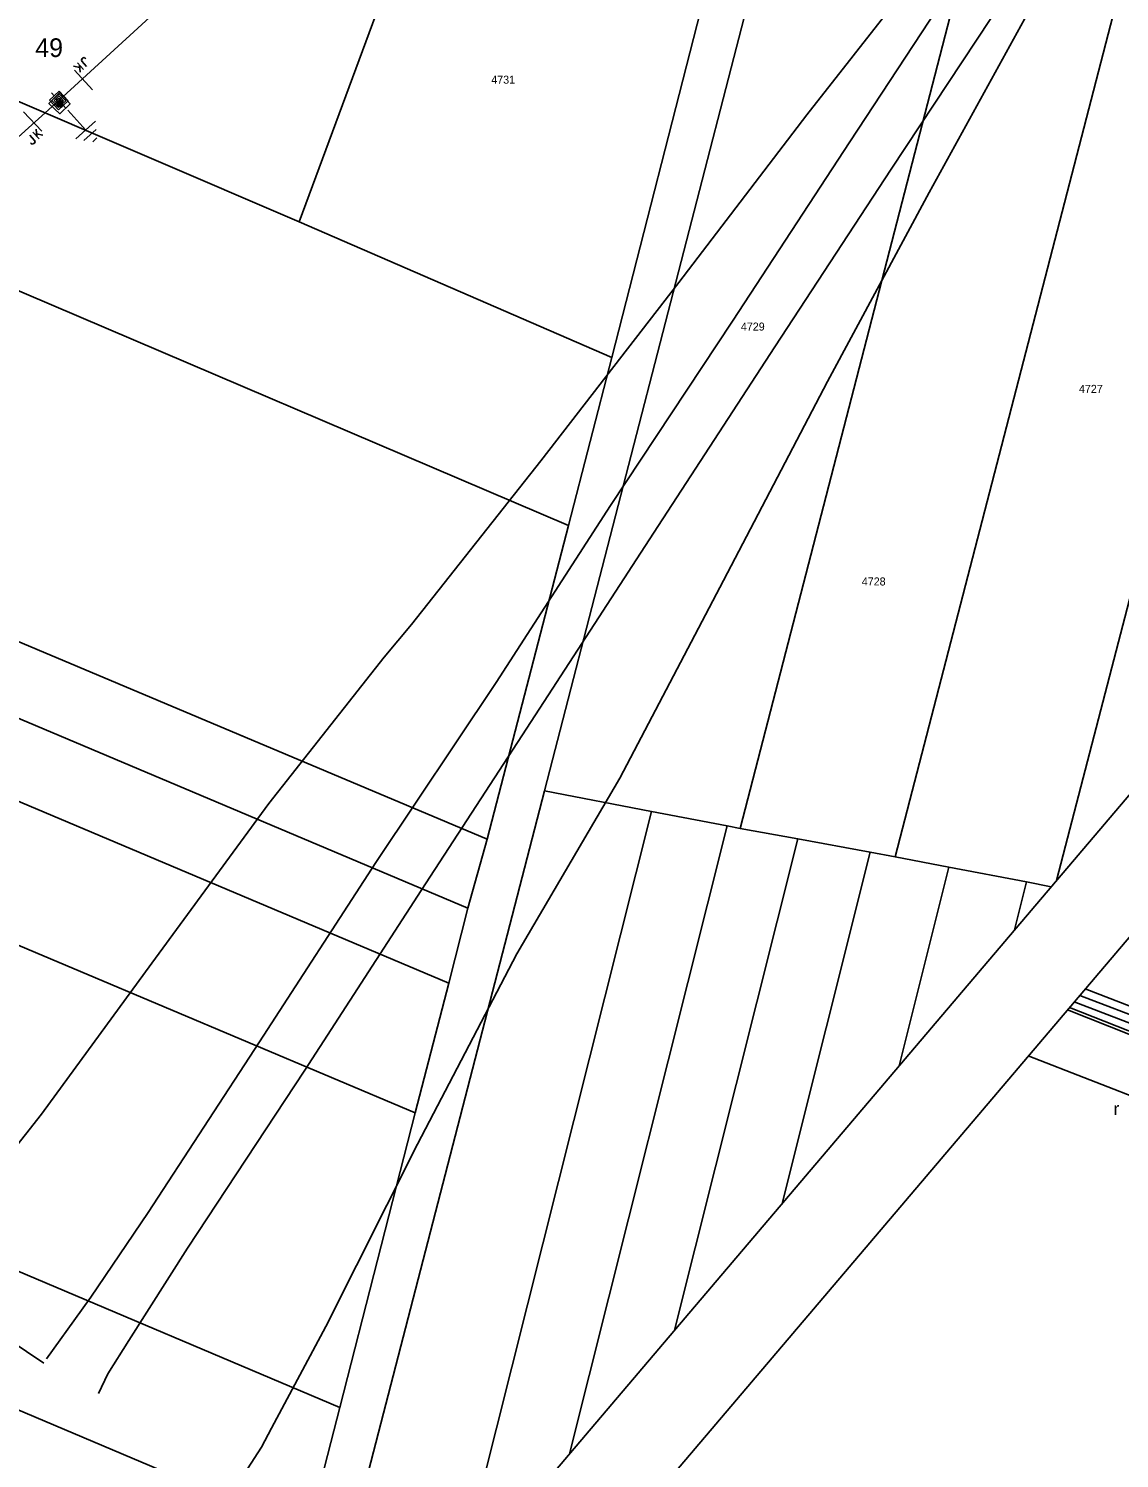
# Model space of a CAD drawing. Extents: x -540150 to -533593, y -1185082 to -1180066.
# Drawn here: x -536015.9 to -535913.7, y -1182345.7 to -1182211.6 of the extents above; entities that cross this region are included whole.
import ezdxf

# ---------------------------------------------------------------- set-up
doc = ezdxf.new("R2010")
doc.units = 0
for name, color, linetype in [('KN_HRAN_PARCEL', 7, 'Continuous'), ('KN_PARC_Č', 7, 'Continuous'), ('rámeček', 7, 'Continuous'), ('Vrstva 1', 7, 'Continuous'), ('Vrstva 11', 7, 'Continuous'), ('Vrstva 13', 7, 'Continuous'), ('Vrstva 14', 7, 'Continuous'), ('Vrstva 15', 7, 'Continuous'), ('Vrstva 18', 7, 'Continuous'), ('Vrstva 2', 7, 'Continuous'), ('Vrstva 25', 7, 'Continuous'), ('Vrstva 36', 7, 'Continuous'), ('Vrstva 7', 7, 'Continuous')]:
    doc.layers.add(name, color=color, linetype=linetype)

# ---------------------------------------------------------------- blocks, each defined once
blk = doc.blocks.new('VN840')
at = {"layer": 'Vrstva 15'}
for points in [[(-0.01, 1.41), (-0.01, -1.09)], [(-1.51, -1.24), (-1.51, -1.15)], [(-1.48, -1.35), (-1.51, -1.24)], [(-1.09, -1.24), (-1.13, -1.35)], [(-1.09, -0.59), (-1.09, -1.24)], [(-0.68, -0.59), (-0.68, -1.42)], [(-0.68, -1.11), (-0.27, -0.59)], [(-0.54, -0.94), (-0.2, -1.42)], [(-1.33, -1.42), (-1.48, -1.35)], [(-1.27, -1.42), (-1.33, -1.42)], [(-1.13, -1.35), (-1.27, -1.42)]]:
    blk.add_lwpolyline(points, dxfattribs=at)
blk = doc.blocks.new('VN810')
at = {"layer": 'Vrstva 14'}
for points in [[(0, -1.25), (0, -3.75)], [(1.25, -3.75), (-1.25, -3.75)], [(0.77, -4.37), (-0.8, -4.37)], [(0, -5), (-0.25, -5)], [(0.27, -5), (0, -5)]]:
    blk.add_lwpolyline(points, dxfattribs=at)
blk = doc.blocks.new('VN470')
at = {"layer": 'Vrstva 2'}
for points in [[(-1.23, 1.22), (1.23, 1.22)], [(-1.23, -1.23), (-1.23, 1.22)], [(-0.92, 0.9), (0.92, 0.9)], [(-0.92, -0.95), (-0.92, 0.9)], [(-0.61, 0.61), (0.61, 0.61)], [(-0.61, -0.62), (-0.61, 0.61)], [(-0.31, -0.27), (-0.31, 0.34)], [(-0.31, 0.34), (0.31, 0.34)], [(0, 1.22), (0, 1.97)], [(0.31, 0.34), (0.31, -0.27)], [(0.61, 0.61), (0.61, -0.62)], [(0.92, 0.9), (0.92, -0.95)], [(1.23, 1.22), (1.23, -1.23)], [(1.23, -1.23), (-1.23, -1.23)], [(0.92, -0.95), (-0.92, -0.95)], [(0.61, -0.62), (-0.61, -0.62)], [(0.31, -0.27), (-0.31, -0.27)], [(0, -1.23), (0, -1.98)]]:
    blk.add_lwpolyline(points, dxfattribs=at)

msp = doc.modelspace()

# ---------------------------------------------------------------- linework, layer by layer
at = {"layer": 'KN_HRAN_PARCEL'}
for p, q in [((-535990.58, -1182229.75), (-535973.6, -1182183.9)), ((-536091.46, -1182186.49), (-535990.58, -1182229.75)), ((-535961.28, -1182242.48), (-535950.03, -1182198.41)), ((-536101.6, -1182200.04), (-535965.35, -1182258.21)), ((-535946.07, -1182199.75), (-535967.59, -1182283.08)), ((-535949.27, -1182286.61), (-535927.35, -1182201.89)), ((-535934.72, -1182289.28), (-535913.75, -1182208.2)), ((-535919.62, -1182291.48), (-535899.65, -1182214.53)), ((-536120.65, -1182225.43), (-535972.96, -1182287.61)), ((-535990.58, -1182229.75), (-535961.28, -1182242.48)), ((-536124.53, -1182230.88), (-535974.77, -1182294.08)), ((-536129.02, -1182236.75), (-535976.56, -1182301.1)), ((-535965.35, -1182258.21), (-535961.28, -1182242.48)), ((-536136.67, -1182246.99), (-535979.71, -1182313.28)), ((-535972.96, -1182287.61), (-535965.35, -1182258.21)), ((-536154.1, -1182270.11), (-535986.76, -1182340.88)), ((-535989.8, -1182352.58), (-536161.48, -1182279.94)), ((-535967.59, -1182283.08), (-535991.72, -1182376.4)), ((-535967.59, -1182283.08), (-535957.58, -1182285.01)), ((-535975.83, -1182357.68), (-535957.58, -1182285.01)), ((-535957.58, -1182285.01), (-535950.47, -1182286.38)), ((-535965.25, -1182345.22), (-535950.47, -1182286.38)), ((-535950.47, -1182286.38), (-535949.27, -1182286.61)), ((-535949.27, -1182286.61), (-535943.86, -1182287.6)), ((-535974.77, -1182294.08), (-535972.96, -1182287.61)), ((-535955.42, -1182333.65), (-535943.86, -1182287.6)), ((-535943.86, -1182287.6), (-535937.06, -1182288.85)), ((-535945.33, -1182321.76), (-535937.06, -1182288.85)), ((-535937.06, -1182288.85), (-535934.72, -1182289.28)), ((-535934.72, -1182289.28), (-535929.69, -1182290.25)), ((-535934.36, -1182308.85), (-535929.69, -1182290.25)), ((-535929.69, -1182290.25), (-535922.43, -1182291.63)), ((-535923.56, -1182296.12), (-535922.43, -1182291.63)), ((-535922.43, -1182291.63), (-535920.13, -1182292.08)), ((-535976.56, -1182301.1), (-535974.77, -1182294.08)), ((-535979.71, -1182313.28), (-535976.56, -1182301.1)), ((-535918.58, -1182303.61), (-535878.33, -1182319.7)), ((-535880.61, -1182324.16), (-535922.26, -1182307.94)), ((-535986.76, -1182340.88), (-535979.71, -1182313.28)), ((-535989.8, -1182352.58), (-535986.76, -1182340.88))]:
    msp.add_line(p, q, dxfattribs=at)
at = {"layer": 'rámeček'}
msp.add_lwpolyline([(-536738.71, -1183256.04), (-536957.47, -1183070.27), (-535604.64, -1181477.18), (-535385.87, -1181662.95)], close=True, dxfattribs=at)
msp.add_lwpolyline([(-535379.29, -1181668.54), (-536732.12, -1183261.63), (-536513.36, -1183447.4), (-535160.52, -1181854.31)], dxfattribs=at)
at = {"layer": 'Vrstva 1'}
msp.add_lwpolyline([(-535558.37, -1181516.47), (-535557.88, -1181544.08), (-535587.84, -1181626.35), (-535619.52, -1181709.12), (-535651.77, -1181794.03), (-535681.12, -1181869.54), (-535710.09, -1181945.05), (-535783.95, -1182011.48), (-535866.19, -1182086.36), (-535938.34, -1182149.87), (-536013.11, -1182218.39), (-536091.77, -1182289.3), (-536171.39, -1182361.64), (-536250.64, -1182434.05), (-536331.09, -1182507.05), (-536410.34, -1182579.17), (-536496.48, -1182657.64), (-536561.1, -1182716.88), (-536627.07, -1182777.54), (-536686.64, -1182832.24), (-536719.16, -1182861.03)], dxfattribs=at)
at = {"layer": 'Vrstva 11'}
for p, q in [((-535917.95, -1182302.86), (-535903.19, -1182308.55)), ((-535916.92, -1182301.65), (-535902.66, -1182307.15))]:
    msp.add_line(p, q, dxfattribs=at)
at = {"layer": 'Vrstva 14'}
for p, q in [((-535930.51, -1182203.75), (-535943, -1182219.74)), ((-535938.97, -1182222.26), (-535927.96, -1182205.45)), ((-535924.1, -1182208.15), (-535935.1, -1182224.82)), ((-535931.56, -1182227.01), (-535921.92, -1182209.52)), ((-535943, -1182219.74), (-535955, -1182235.43)), ((-535949.97, -1182239.07), (-535938.97, -1182222.26)), ((-535935.1, -1182224.82), (-535946.01, -1182241.47)), ((-535941.06, -1182244.72), (-535931.56, -1182227.01)), ((-535955, -1182235.43), (-535967.93, -1182252.17)), ((-535961.42, -1182256.33), (-535949.97, -1182239.07)), ((-535946.01, -1182241.47), (-535957.38, -1182258.94)), ((-535950.81, -1182263.36), (-535941.06, -1182244.72)), ((-535967.93, -1182252.17), (-535980.04, -1182267.51)), ((-535972.13, -1182272.94), (-535961.42, -1182256.33)), ((-535957.38, -1182258.94), (-535968.85, -1182276.58)), ((-535960.53, -1182281.89), (-535950.81, -1182263.36)), ((-535980.04, -1182267.51), (-535982.61, -1182270.57)), ((-535982.61, -1182270.57), (-535993.42, -1182284.29)), ((-535983.39, -1182289.82), (-535972.13, -1182272.94)), ((-535968.85, -1182276.58), (-535979.14, -1182292.43)), ((-535970.17, -1182298.36), (-535960.53, -1182281.89)), ((-535993.42, -1182284.29), (-536004.39, -1182299.23)), ((-535993.42, -1182284.29), (-536004.39, -1182299.23)), ((-535994.3, -1182306.61), (-535983.39, -1182289.82)), ((-535979.14, -1182292.43), (-535990.06, -1182309.28)), ((-535979.48, -1182316.19), (-535970.17, -1182298.36)), ((-536004.39, -1182299.23), (-536014.74, -1182313.39)), ((-535917.43, -1182302.26), (-535902.93, -1182307.85)), ((-535903.39, -1182309.33), (-535918.39, -1182303.39)), ((-536004.72, -1182322.6), (-535994.3, -1182306.61)), ((-536004.72, -1182322.6), (-535994.3, -1182306.61)), ((-535990.06, -1182309.28), (-536001.05, -1182325.96)), ((-535990.06, -1182309.28), (-536001.05, -1182325.96)), ((-535988.08, -1182333.28), (-535979.48, -1182316.19)), ((-536001.05, -1182325.96), (-536006.53, -1182334.61)), ((-536014.27, -1182336.34), (-536010.98, -1182331.76)), ((-535993.17, -1182342.82), (-535988.08, -1182333.28)), ((-536006.53, -1182334.61), (-536008.52, -1182337.74)), ((-536008.52, -1182337.74), (-536009.38, -1182339.58)), ((-535994.12, -1182344.59), (-535993.17, -1182342.82)), ((-535997.59, -1182349.99), (-535994.12, -1182344.59)), ((-535997.59, -1182349.99), (-535994.12, -1182344.59))]:
    msp.add_line(p, q, dxfattribs=at)
for points in [[(-536014.74, -1182313.39), (-536021.09, -1182321.46), (-536022.87, -1182323.92)], [(-536010.98, -1182331.76), (-536010.11, -1182330.54), (-536004.72, -1182322.6)], [(-536026.48, -1182328.72), (-536026.23, -1182328.89), (-536026.2, -1182328.9), (-536014.51, -1182336.74)]]:
    msp.add_lwpolyline(points, dxfattribs=at)
at = {"layer": 'Vrstva 25'}
for points in [[(-536013.27, -1182218.94), (-536012.77, -1182218.94), (-536012.77, -1182218.44), (-536013.27, -1182218.44)], [(-536013.22, -1182218.89), (-536012.82, -1182218.89), (-536012.82, -1182218.49), (-536013.22, -1182218.49)], [(-536013.17, -1182218.84), (-536012.87, -1182218.84), (-536012.87, -1182218.54), (-536013.17, -1182218.54)], [(-536013.12, -1182218.79), (-536012.92, -1182218.79), (-536012.92, -1182218.59), (-536013.12, -1182218.59)], [(-536013.07, -1182218.74), (-536012.97, -1182218.74), (-536012.97, -1182218.64), (-536013.07, -1182218.64)]]:
    msp.add_lwpolyline(points, close=True, dxfattribs=at)
at = {"layer": 'Vrstva 7'}
msp.add_lwpolyline([(-536013.02, -1182217.64), (-536012.04, -1182218.7), (-536013.02, -1182219.63), (-536014.03, -1182218.68), (-536013.02, -1182217.64)], dxfattribs=at)

# ---------------------------------------------------------------- block references
at = {"layer": 'Vrstva 13', "xscale": 0.49999999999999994, "yscale": 0.5, "rotation": 43.137561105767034}
msp.add_blockref('VN470', (-536013.11, -1182218.39), dxfattribs=at)
at = {"layer": 'Vrstva 15', "rotation": 42.333600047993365}
msp.add_blockref('VN810', (-536013.11, -1182218.38), dxfattribs=at)
at = {"layer": 'Vrstva 18'}
for p, rotation in [((-536010.9, -1182216.36), -137.49868050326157), ((-536015.43, -1182220.47), 43.137561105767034)]:
    msp.add_blockref('VN840', p, dxfattribs=dict(at, rotation=rotation))

# ---------------------------------------------------------------- texts
at = {"layer": 'KN_PARC_Č'}
for s, p in [('4731', (-535972.58, -1182216.81)), ('4729', (-535949.19, -1182239.95)), ('4727', (-535917.51, -1182245.79)), ('4728', (-535937.86, -1182263.84))]:
    msp.add_text(s, height=0.75, dxfattribs=at).set_placement(p)
at = {"layer": 'Vrstva 14'}
msp.add_text('49', height=1.75, dxfattribs=at).set_placement((-536015.31, -1182214.31))
at = {"layer": 'Vrstva 36'}
msp.add_text('r', height=1.2, dxfattribs=at).set_placement((-535914.27, -1182313.48))

doc.saveas('drawing.dxf')
